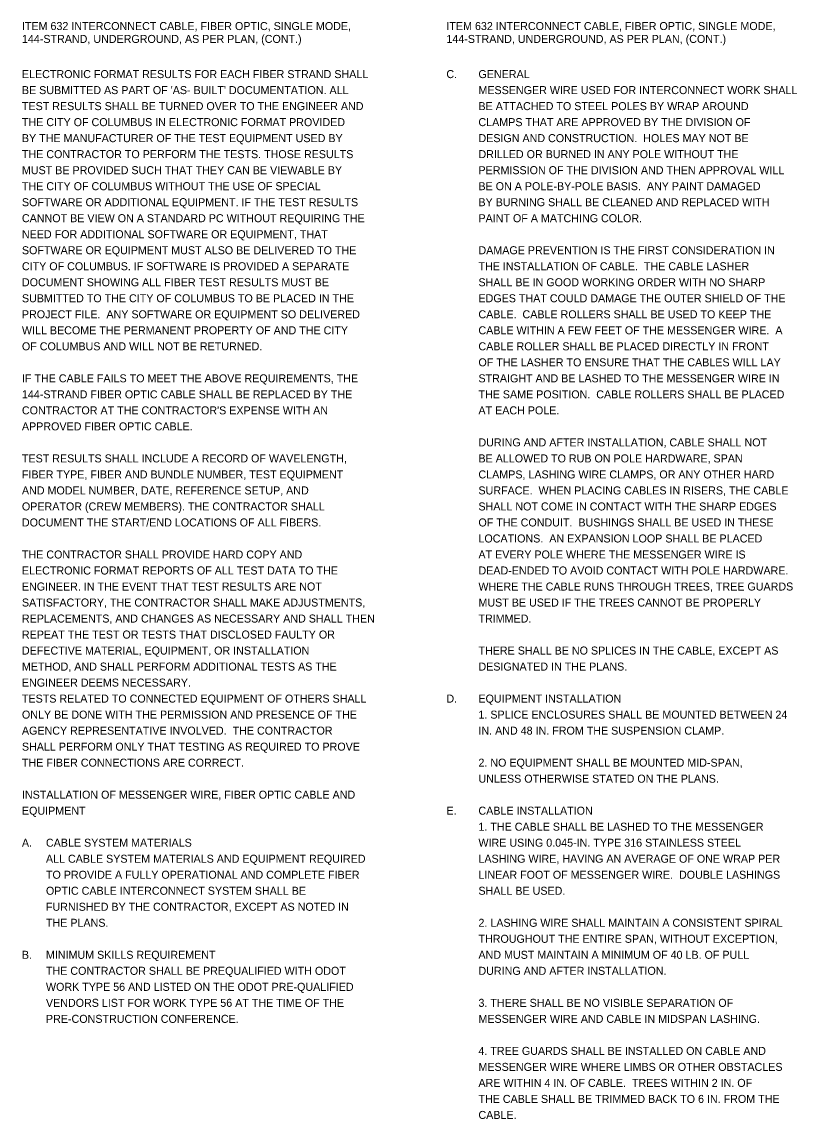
# Model space of a CAD drawing. Extents: x -15.1 to 53.7, y -46.4 to 36.
# Drawn here: x 17.23 to 30.78, y 16.77 to 35.96 of the extents above; entities that cross this region are included whole.
import ezdxf

# ---------------------------------------------------------------- set-up
doc = ezdxf.new("R2010")
doc.units = 0
doc.layers.add('SH_Data', color=7, linetype='Continuous')
doc.layers.add('SH_Text', color=7, linetype='Continuous')

msp = doc.modelspace()

# ---------------------------------------------------------------- texts
at = {"layer": 'SH_Data'}
for s, p in [('ITEM 632 INTERCONNECT CABLE, FIBER OPTIC, SINGLE MODE, ', (17.234, 35.816)), ('ITEM 632 INTERCONNECT CABLE, FIBER OPTIC, SINGLE MODE, ', (24.654, 35.816)), ('144-STRAND, UNDERGROUND, AS PER PLAN, (CONT.)', (17.234, 35.591)), ('144-STRAND, UNDERGROUND, AS PER PLAN, (CONT.)', (24.654, 35.591))]:
    msp.add_text(s, height=0.14, dxfattribs=at).set_placement(p)
at = {"layer": 'SH_Text'}
for s, p in [('ELECTRONIC FORMAT RESULTS FOR EACH FIBER STRAND SHALL ', (17.234, 34.976)), ('C.', (24.654, 34.976)), ('GENERAL', (25.214, 34.976)), ("BE SUBMITTED AS PART OF 'AS- BUILT' DOCUMENTATION. ALL ", (17.234, 34.696)), ('MESSENGER WIRE USED FOR INTERCONNECT WORK SHALL ', (25.214, 34.696)), ('TEST RESULTS SHALL BE TURNED OVER TO THE ENGINEER AND ', (17.234, 34.416)), ('BE ATTACHED TO STEEL POLES BY WRAP AROUND ', (25.214, 34.416)), ('THE CITY OF COLUMBUS IN ELECTRONIC FORMAT PROVIDED ', (17.234, 34.136)), ('CLAMPS THAT ARE APPROVED BY THE DIVISION OF ', (25.214, 34.136)), ('BY THE MANUFACTURER OF THE TEST EQUIPMENT USED BY ', (17.234, 33.856)), ('DESIGN AND CONSTRUCTION.  HOLES MAY NOT BE ', (25.214, 33.856)), ('THE CONTRACTOR TO PERFORM THE TESTS. THOSE RESULTS ', (17.234, 33.576)), ('DRILLED OR BURNED IN ANY POLE WITHOUT THE ', (25.214, 33.576)), ('MUST BE PROVIDED SUCH THAT THEY CAN BE VIEWABLE BY ', (17.234, 33.296)), ('PERMISSION OF THE DIVISION AND THEN APPROVAL WILL ', (25.214, 33.296)), ('THE CITY OF COLUMBUS WITHOUT THE USE OF SPECIAL ', (17.234, 33.016)), ('BE ON A POLE-BY-POLE BASIS.  ANY PAINT DAMAGED ', (25.214, 33.016)), ('SOFTWARE OR ADDITIONAL EQUIPMENT. IF THE TEST RESULTS ', (17.234, 32.736)), ('BY BURNING SHALL BE CLEANED AND REPLACED WITH ', (25.214, 32.736)), ('CANNOT BE VIEW ON A STANDARD PC WITHOUT REQUIRING THE ', (17.234, 32.456)), ('PAINT OF A MATCHING COLOR.', (25.214, 32.456)), ('NEED FOR ADDITIONAL SOFTWARE OR EQUIPMENT, THAT ', (17.234, 32.176)), ('SOFTWARE OR EQUIPMENT MUST ALSO BE DELIVERED TO THE ', (17.234, 31.896)), ('DAMAGE PREVENTION IS THE FIRST CONSIDERATION IN ', (25.214, 31.896)), ('CITY OF COLUMBUS. IF SOFTWARE IS PROVIDED A SEPARATE ', (17.234, 31.616)), ('THE INSTALLATION OF CABLE.  THE CABLE LASHER ', (25.214, 31.616)), ('DOCUMENT SHOWING ALL FIBER TEST RESULTS MUST BE ', (17.234, 31.336)), ('SHALL BE IN GOOD WORKING ORDER WITH NO SHARP ', (25.214, 31.336)), ('SUBMITTED TO THE CITY OF COLUMBUS TO BE PLACED IN THE ', (17.234, 31.056)), ('EDGES THAT COULD DAMAGE THE OUTER SHIELD OF THE ', (25.214, 31.056)), ('PROJECT FILE.  ANY SOFTWARE OR EQUIPMENT SO DELIVERED ', (17.234, 30.776)), ('CABLE.  CABLE ROLLERS SHALL BE USED TO KEEP THE ', (25.214, 30.776)), ('WILL BECOME THE PERMANENT PROPERTY OF AND THE CITY ', (17.234, 30.496)), ('CABLE WITHIN A FEW FEET OF THE MESSENGER WIRE.  A ', (25.214, 30.496)), ('OF COLUMBUS AND WILL NOT BE RETURNED.', (17.234, 30.216)), ('CABLE ROLLER SHALL BE PLACED DIRECTLY IN FRONT ', (25.214, 30.216)), ('OF THE LASHER TO ENSURE THAT THE CABLES WILL LAY ', (25.214, 29.936)), ('IF THE CABLE FAILS TO MEET THE ABOVE REQUIREMENTS, THE ', (17.234, 29.656)), ('STRAIGHT AND BE LASHED TO THE MESSENGER WIRE IN ', (25.214, 29.656)), ('144-STRAND FIBER OPTIC CABLE SHALL BE REPLACED BY THE ', (17.234, 29.376)), ('THE SAME POSITION.  CABLE ROLLERS SHALL BE PLACED ', (25.214, 29.376)), ("CONTRACTOR AT THE CONTRACTOR'S EXPENSE WITH AN ", (17.234, 29.096)), ('AT EACH POLE.', (25.214, 29.096)), ('APPROVED FIBER OPTIC CABLE.', (17.234, 28.816)), ('DURING AND AFTER INSTALLATION, CABLE SHALL NOT ', (25.214, 28.536)), ('TEST RESULTS SHALL INCLUDE A RECORD OF WAVELENGTH, ', (17.234, 28.256)), ('BE ALLOWED TO RUB ON POLE HARDWARE, SPAN ', (25.214, 28.256)), ('FIBER TYPE, FIBER AND BUNDLE NUMBER, TEST EQUIPMENT ', (17.234, 27.976)), ('CLAMPS, LASHING WIRE CLAMPS, OR ANY OTHER HARD ', (25.214, 27.976)), ('AND MODEL NUMBER, DATE, REFERENCE SETUP, AND ', (17.234, 27.696)), ('SURFACE.  WHEN PLACING CABLES IN RISERS, THE CABLE ', (25.214, 27.696)), ('OPERATOR (CREW MEMBERS). THE CONTRACTOR SHALL ', (17.234, 27.416)), ('SHALL NOT COME IN CONTACT WITH THE SHARP EDGES ', (25.214, 27.416)), ('DOCUMENT THE START/END LOCATIONS OF ALL FIBERS.', (17.234, 27.136)), ('OF THE CONDUIT.  BUSHINGS SHALL BE USED IN THESE ', (25.214, 27.136)), ('LOCATIONS.  AN EXPANSION LOOP SHALL BE PLACED ', (25.214, 26.856)), ('THE CONTRACTOR SHALL PROVIDE HARD COPY AND ', (17.234, 26.576)), ('AT EVERY POLE WHERE THE MESSENGER WIRE IS ', (25.214, 26.576)), ('ELECTRONIC FORMAT REPORTS OF ALL TEST DATA TO THE ', (17.234, 26.296)), ('DEAD-ENDED TO AVOID CONTACT WITH POLE HARDWARE.  ', (25.214, 26.296)), ('ENGINEER. IN THE EVENT THAT TEST RESULTS ARE NOT ', (17.234, 26.016)), ('WHERE THE CABLE RUNS THROUGH TREES, TREE GUARDS ', (25.214, 26.016)), ('SATISFACTORY, THE CONTRACTOR SHALL MAKE ADJUSTMENTS, ', (17.234, 25.736)), ('MUST BE USED IF THE TREES CANNOT BE PROPERLY ', (25.214, 25.736)), ('REPLACEMENTS, AND CHANGES AS NECESSARY AND SHALL THEN ', (17.234, 25.456)), ('TRIMMED.', (25.214, 25.456)), ('REPEAT THE TEST OR TESTS THAT DISCLOSED FAULTY OR ', (17.234, 25.176)), ('DEFECTIVE MATERIAL, EQUIPMENT, OR INSTALLATION ', (17.234, 24.896)), ('THERE SHALL BE NO SPLICES IN THE CABLE, EXCEPT AS ', (25.214, 24.896)), ('METHOD, AND SHALL PERFORM ADDITIONAL TESTS AS THE ', (17.234, 24.616)), ('DESIGNATED IN THE PLANS.', (25.214, 24.616)), ('ENGINEER DEEMS NECESSARY.', (17.234, 24.336)), ('TESTS RELATED TO CONNECTED EQUIPMENT OF OTHERS SHALL ', (17.234, 24.056)), ('D.', (24.654, 24.056)), ('EQUIPMENT INSTALLATION', (25.214, 24.056)), ('ONLY BE DONE WITH THE PERMISSION AND PRESENCE OF THE ', (17.234, 23.776)), ('1. SPLICE ENCLOSURES SHALL BE MOUNTED BETWEEN 24 ', (25.214, 23.776)), ('AGENCY REPRESENTATIVE INVOLVED.  THE CONTRACTOR ', (17.234, 23.496)), ('IN. AND 48 IN. FROM THE SUSPENSION CLAMP.', (25.214, 23.496)), ('SHALL PERFORM ONLY THAT TESTING AS REQUIRED TO PROVE ', (17.234, 23.216)), ('THE FIBER CONNECTIONS ARE CORRECT.', (17.234, 22.936)), ('2. NO EQUIPMENT SHALL BE MOUNTED MID-SPAN, ', (25.214, 22.936)), ('UNLESS OTHERWISE STATED ON THE PLANS.', (25.214, 22.656)), ('INSTALLATION OF MESSENGER WIRE, FIBER OPTIC CABLE AND ', (17.234, 22.376)), ('EQUIPMENT ', (17.234, 22.096)), ('E.', (24.654, 22.096)), ('CABLE INSTALLATION', (25.214, 22.096)), ('1. THE CABLE SHALL BE LASHED TO THE MESSENGER ', (25.214, 21.816)), ('A.', (17.234, 21.536)), ('CABLE SYSTEM MATERIALS', (17.654, 21.536)), ('WIRE USING 0.045-IN. TYPE 316 STAINLESS STEEL ', (25.214, 21.536)), ('ALL CABLE SYSTEM MATERIALS AND EQUIPMENT REQUIRED ', (17.654, 21.256)), ('LASHING WIRE, HAVING AN AVERAGE OF ONE WRAP PER ', (25.214, 21.256)), ('TO PROVIDE A FULLY OPERATIONAL AND COMPLETE FIBER ', (17.654, 20.976)), ('LINEAR FOOT OF MESSENGER WIRE.  DOUBLE LASHINGS ', (25.214, 20.976)), ('OPTIC CABLE INTERCONNECT SYSTEM SHALL BE ', (17.654, 20.696)), ('SHALL BE USED.', (25.214, 20.696)), ('FURNISHED BY THE CONTRACTOR, EXCEPT AS NOTED IN ', (17.654, 20.416)), ('THE PLANS.', (17.654, 20.136)), ('2. LASHING WIRE SHALL MAINTAIN A CONSISTENT SPIRAL ', (25.214, 20.136)), ('THROUGHOUT THE ENTIRE SPAN, WITHOUT EXCEPTION, ', (25.214, 19.856)), ('B.', (17.234, 19.576)), ('MINIMUM SKILLS REQUIREMENT', (17.654, 19.576)), ('AND MUST MAINTAIN A MINIMUM OF 40 LB. OF PULL ', (25.214, 19.576)), ('THE CONTRACTOR SHALL BE PREQUALIFIED WITH ODOT ', (17.654, 19.296)), ('DURING AND AFTER INSTALLATION.', (25.214, 19.296)), ('WORK TYPE 56 AND LISTED ON THE ODOT PRE-QUALIFIED ', (17.654, 19.016)), ('VENDORS LIST FOR WORK TYPE 56 AT THE TIME OF THE ', (17.654, 18.736)), ('3. THERE SHALL BE NO VISIBLE SEPARATION OF ', (25.214, 18.736)), ('PRE-CONSTRUCTION CONFERENCE.', (17.654, 18.456)), ('MESSENGER WIRE AND CABLE IN MIDSPAN LASHING.', (25.214, 18.456)), ('4. TREE GUARDS SHALL BE INSTALLED ON CABLE AND ', (25.214, 17.896)), ('MESSENGER WIRE WHERE LIMBS OR OTHER OBSTACLES ', (25.214, 17.616)), ('ARE WITHIN 4 IN. OF CABLE.  TREES WITHIN 2 IN. OF ', (25.214, 17.336)), ('THE CABLE SHALL BE TRIMMED BACK TO 6 IN. FROM THE ', (25.214, 17.056)), ('CABLE.', (25.214, 16.776))]:
    msp.add_text(s, height=0.14, dxfattribs=at).set_placement(p)

doc.saveas('drawing.dxf')
